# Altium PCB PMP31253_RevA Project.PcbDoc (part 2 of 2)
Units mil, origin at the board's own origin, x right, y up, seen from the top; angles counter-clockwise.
Board outline 7112.5 x 1987.5 mil, 2 copper layers (Top Layer, Bottom Layer), stack 62 mil thick; 96 components, 51 nets, 198 pads, 16 vias.
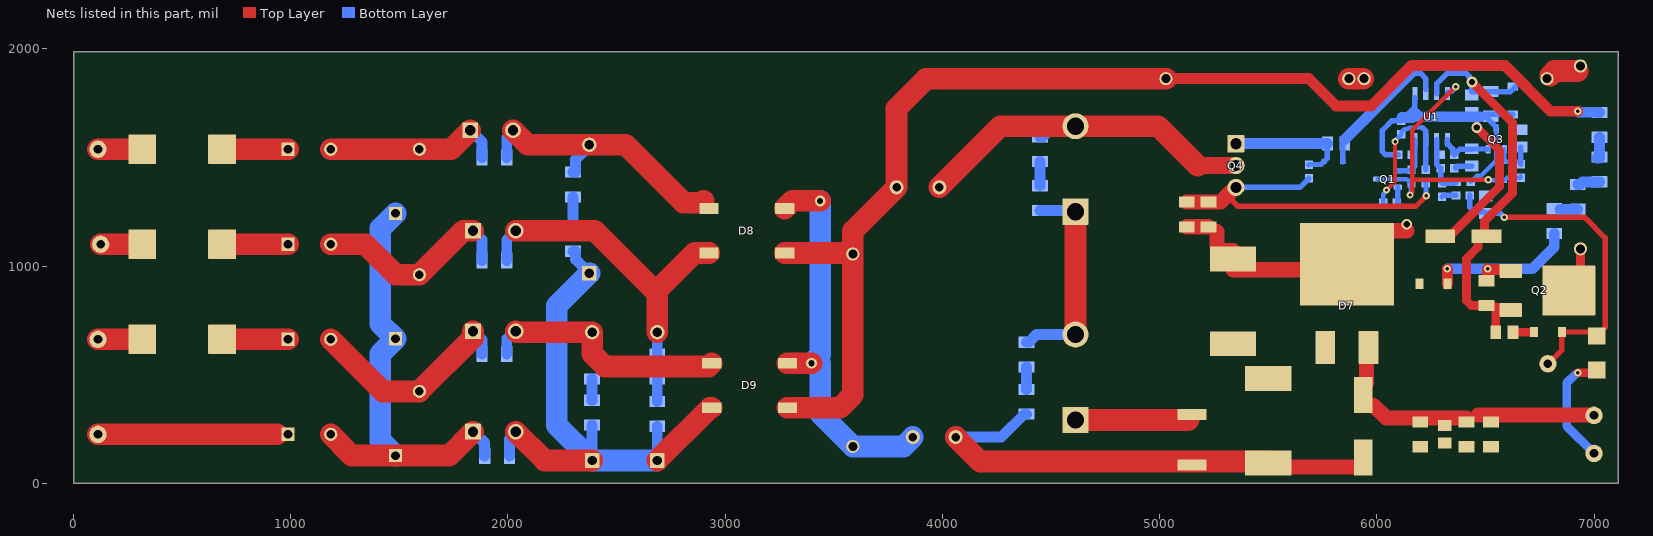
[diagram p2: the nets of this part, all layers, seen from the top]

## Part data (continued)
R20 R31 R39 R44: library part CMP-0087547-1, "RESISTOR, 5W 5% 22R", Manufacturer="TE Connectivity", Power_W=5W, TempCo=300ppm/°C, Tolerance_%=5%
R21 R32 R40 R45: library part CMP-0016578-3, "RES, 10.0 k, 1%, 0.5 W, AEC-Q200 Grade 0, 1206", Manufacturer=Vishay-Dale, Power_W=500mW, Supplier Part Number 1=541-10.0KUCT-ND, TempCo="100 ppm/C", Tolerance_%=1%, Value2=0.5W, Value_Code=10k0, ValueDisplayed=10.0k
R22 R25 R33 R36 R41 R43: library part CMP-0018574-3, "RES, 5%, 1206", Manufacturer=Vishay-Dale, PartNumber=TBD, Power_W=250mW, TempCo="200 ppm/C", Tolerance_%=5%, Value2=0.25W, Value_Code=100k, ValueDisplayed=DNP
R23 R35 R42: library part CMP-0001478-1, "750 V 2.5 kA Varistor 1 Circuit Through Hole Disc 10mm", Clamping Voltage=1240V, Digikey Part Number=495-4644-ND, Manufacturer=TDK, Mouser Part Number=871-B72210S461K101, Operating Temperature Range="-40°C to +105°C", Part Number=B72210S0461K101, ValueDisplayed=150pF, Varistor Voltage=750V, Voltage Tolerance=10%
R24: library part CMP-0017792-3, "RES, 0.56, 1%, 0.25 W, AEC-Q200 Grade 0, 1206", Manufacturer=Panasonic, Power_W=250mW, Supplier Part Number 1=P.56RCT-ND, TempCo="250 ppm/C", Tolerance_%=1%, Value2=0.25W, Value_Code=R560, ValueDisplayed=0.56
R26: library part CMP-0017774-1, Manufacturer=Panasonic, PartNumber=ERJ-8RQF1R2V, Power_W=250mW, Supplier Part Number 1=P1.2RCT-ND, TempCo="200 ppm/C", Tolerance_%=1%, Value2=0.25W, Value_Code=1R20
R27 R30 R34 R38: library part CMP-0018574-3, "RES, 5%, 1206", Manufacturer=Vishay-Dale, PartNumber=750k, Power_W=250mW, TempCo="200 ppm/C", Tolerance_%=5%, Value2=0.25W, Value_Code=100k
R28 R29: library part CMP-0018703-3, "RES, 5.1 k, 5%, 0.25 W, AEC-Q200 Grade 0, 1206", Manufacturer=Vishay-Dale, Power_W=250mW, Supplier Part Number 1=541-5.1KECT-ND, TempCo="200 ppm/C", Tolerance_%=5%, Value2=0.25W, Value_Code=5k10, ValueDisplayed=5.1k
R37: library part CMP-0078952-1, "RES, 15, 1%, 2 W, 2512", Manufacturer=Bourns, Power_W=2W, Supplier Part Number 1=CRM2512-FX-2000ELF-ND, TempCo="100 ppm/C", Tolerance_%=1%, Value_Code=200R, ValueDisplayed=SHORT
TP1 TP2 TP4 TP5 TP6 TP7: library part CMP-0055137-2, "Test Point, Miniature, Red, TH", Color=Red, Manufacturer="Keystone Electronics", Supplier Part Number 1=36-5000-ND
TP3: library part CMP-0055138-2, "Test Point, Miniature, Black, TH", Color=Black, Manufacturer="Keystone Electronics", Supplier Part Number 1=36-5001-ND
U1: library part CMP-0001407-1, "Low-Power Current-Mode High-Performance PWM Controller for Si and SiC MOSFETs", Digikey Part Number=296-UCC28C55DRCT-ND, Manufacturer="Texas Instruments", Max Supply Voltage=28V, Mouser Part Number=595-UCC28C55DR, Nominal Supply Current=1.3mA, Operating Temperature Range="-40°C to +125°C", Switching Frequency=1MHz

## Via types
v1: diameter 34, hole 16, Top Layer to Bottom Layer, 11 vias
v2: diameter 50, hole 28, Top Layer to Bottom Layer, 5 vias

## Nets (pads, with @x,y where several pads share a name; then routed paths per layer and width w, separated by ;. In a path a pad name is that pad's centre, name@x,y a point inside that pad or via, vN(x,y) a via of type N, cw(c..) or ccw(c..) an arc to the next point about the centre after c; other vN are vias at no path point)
12Vout: C12.2 C13.2 C14.2 D1.2 L4.1 L6.2 R28.1 R29.1 R37.1 R38.1 TP5.1 | length 2809.6
  Top Layer w40: v1(6925,508.07) 6999.31,508.07 D1.2@7012.5,521.26
  Top Layer w70: 5612.5,75 5929.19,75 5937.5,83.31 C14.2@5937.5,118.8
  Top Layer w100: L6.2@4062.5,212.5 4175,100 R37.1@5150,100 ; 5218.41,100 R37.1@5150,100 ; L4.1@5500,99.7 5243.7,99.7 5243.41,100 R37.1@5150,100
  Bottom Layer w40: v1@6912.5,500 6875,462.5 6875,262.5 TP5.1@7000,137.5
  Bottom Layer w50: L6.2@4060.93,212.5 4271.26,212.5 4376.67,317.91 R38.1@4387.5,317.91
COMP: C5.2 C7.2 Q3.2 U1.1 | length 234.6
  Bottom Layer w25: U1.1@6325,1581.2 6325,1563.88 6349.31,1539.57 6349.31,1518.7 6355.51,1512.5 C5.2@6356.5,1512.5 6357.48,1512.5 6367.41,1522.43 6367.41,1523.42 6382.06,1538.06 C7.2@6435.56,1538.06 ; C7.2@6451.25,1538.75 6511.81,1538.75 6512.5,1538.06 Q3.2@6512.5,1537.5
CS: Q4.3 R17.1 R19.2 R24.2 R26.1 | length 1626.1
  Top Layer w25: 5315.06,1328.35 5315.06,1321.26 5361.32,1275 6179.17,1275 v1(6227.7,1323.52)
  Top Layer w70: R26.1@5125,1294.59 R24.2@5225,1294.59 5281.3,1294.59 5315.06,1328.35 5348.82,1362.11 Q4.3@5351.18,1362.11
  Bottom Layer w25: Q4.3@5351.18,1362.11 5646.4,1362.11 5687.5,1403.21 R19.2@5687.5,1404.19 ; R17.1@6225,1381 6226.35,1379.66 6226.35,1324.87 v1(6227.7,1323.52)
FB: C1.1 D1.1 D2.2 R16.1 TP1.1 | length 1547.1
  Top Layer w25: v1(6587.5,1223.56) 6957.94,1223.56 7051.4,1130.1 7051.4,717.64 D1.1@7012.5,678.74 6995.01,696.23 D2.2@6851.97,696.23 6851.97,614.47 TP1.1@6787.5,550
  Bottom Layer w25: R16.1@6428.47,1323.89 R16.1@6427.5,1324.87 6427.5,1272.46 6450,1249.96 6493.04,1249.96 C1.1@6500.89,1242.12 6568.7,1242.12 6587.26,1223.56 v1(6587.5,1223.56) v1@6585.9,1225.16
HV_IN: C15.1 D8.1 D9.1 L2.1 R6.2 R11.2 | length 5553.4
  Top Layer w50: R6.2@5029.13,1862.5 5687.5,1862.5 5812.5,1737.5 5975,1737.5 6160,1922.5 6590,1922.5 6800,1712.5 v1(6925,1712.5)
  Top Layer w100: D8.1@3274.5,1060.14 3582.78,1060.14 C15.1@3587.5,1055.41 ; D9.1@3287,347.64 3528.92,347.64 3587.5,406.22 C15.1@3587.5,1055.41 ; R6.2@5029.13,1862.5 3925,1862.5 3789.07,1726.57 L2.1@3789.07,1362.5 3587.5,1160.93 C15.1@3587.5,1055.41
  Bottom Layer w50: v1(6925,1712.5) 6929.82,1707.68 7024.41,1707.68 R11.2@7025,1707.09
NetC2_1: C2.1 C3.1 C6.1 D4.1 Q2.3 R2.1 R7.1 U1.7 | length 2025.7
  Top Layer w40: v2(6437.5,1846.9) 6625,1659.4 6625,1335 6495.56,1205.56 6495.56,1149 6489.02,1149 6466.02,1126 6466.02,1087.5 6412.5,1033.98 6412.5,841.34 6435.93,817.91 R7.1@6504.59,817.91 6510.18,812.32 6546.03,812.32 6547.5,810.85 ; C6.1@6504.59,1144 C6.1@6512.5,1144 ; R2.1@6547.5,695.24 6547.5,810.85 ; Q2.3@6616.14,797.74 6604.65,809.23 6549.12,809.23 6547.5,810.85
  Bottom Layer w25: U1.7@6275,1793.8 6275.69,1794.49 6275.69,1838.19 6325,1887.5 6410.42,1887.5 6425.07,1872.86 6425.07,1866.1 6437.5,1853.66 v2(6437.5,1846.9) 6437.5,1802.5 6615,1802.5 D4.1@6637.5,1825
NetC4_1: C4.1 Q1.1 R1.1 U1.4 | length 209.1
  Bottom Layer w25: Q1.1@6097.24,1437.4 6097.93,1438.09 6161.91,1438.09 R1.1@6162.5,1437.5 ; R1.1@6160.36,1444 6160.36,1444.98 6175,1459.63 U1.4@6175,1581.2
NetC5_1: C5.1 R12.2 R13.2 R14.2 U1.2 | length 260.2
  Bottom Layer w25: U1.2@6275,1581.2 6275,1467.52 R14.2@6287.5,1455.02 ; R12.2@6293.5,1388.98 R14.2@6293.5,1450 ; R12.2@6300,1381.5 6361.32,1381.5 6362.5,1382.68 R13.2@6362.5,1387.5
NetC7_1: C7.1 R14.1 | length 82.1
  Bottom Layer w25: R14.1@6362.5,1450 6362.5,1455.02 6367.48,1460 C7.1@6437.5,1460
NetC8_1: C8.1 D3.2 Q3.1 R3.1 | length 204.7
  Bottom Layer w20: Q3.1@6587.3,1537.5 6587.3,1481 R3.1@6657.03,1481
  Bottom Layer w25: R3.1@6662.5,1469 6662.5,1481 C8.1@6662.5,1547.5
NetC9_1: C9.1 R15.1 R17.2 U1.3 | length 650.9
  Top Layer w20: v1(6044.51,1350) 6083.8,1389.29 v1(6083.8,1573.03)
  Bottom Layer w20: R15.1@6029.19,1291.88 6029.19,1330.89 6044.51,1346.21 v1(6044.51,1350) ; v1(6083.8,1573.03) 6083.8,1576.32 6112.5,1605.02 C9.1@6112.5,1606 ; C9.1@6114.57,1616.43 cw(c6133.28,1609.37) 6132.2,1629.34 ccw(c6131.2,1649.31) 6143.37,1633.44 cw(c6155.45,1617.5) 6155.39,1637.5 6209.67,1637.5
  Bottom Layer w25: 6209.67,1637.5 6224.31,1622.86 6224.31,1581.89 U1.3@6225,1581.2 R17.2@6225,1444
NetC10_1: C10.1 C17.1 C18.1 D9.4 L8.2 R25.1 R36.1 R43.1 R45.2 | length 2633.1
  Top Layer w100: L8.2@2035.93,237.5 2168.7,104.72 C18.1@2387.5,104.72 ; C17.1@2687.5,104.72 2930.41,347.64 D9.4@2938,347.64
  Bottom Layer w50: R45.2@2007.09,125 2007.68,125.59 2007.68,203.07 2035.93,231.32 L8.2@2035.93,237.5 ; R25.1@2300,1067.91 2310.83,1067.91 2311.42,1067.32 2311.42,1030.81 C10.1@2375,967.22 ; C18.1@2387.5,104.72 R43.1@2387.5,267.91 ; C17.1@2687.5,104.72 R36.1@2687.5,262.5
  Bottom Layer w100: C10.1@2375,967.22 2225,817.22 2225,267.22 C18.1@2387.5,104.72 C17.1@2687.5,104.72
NetC10_2: C10.2 D8.3 L1.2 R21.2 R22.2 | length 1324.5
  Top Layer w100: L1.2@2023.43,1625 2090.65,1557.78 C10.2@2375,1557.78 2542.22,1557.78 2808.58,1291.42 2891.42,1291.42 2900,1300
  Bottom Layer w50: R21.2@1994.59,1500 1994.59,1589.98 2023.43,1618.82 L1.2@2023.43,1625 L1.2@2019.06,1620.63 ; R22.2@2300,1432.09 2310.83,1432.09 2311.42,1432.68 2311.42,1489.61 2375,1553.19 C10.2@2375,1557.78
NetC11_1: C11.1 C16.2 R30.1 R34.2 | length 969.9
  Top Layer w100: C16.2@4612.5,684.35 C11.1@4612.5,1250
  Bottom Layer w50: R34.2@4387.5,649.31 4398.33,649.31 4433.37,684.35 C16.2@4612.5,684.35 ; R30.1@4450,1255.41 4450.59,1254.82 4607.68,1254.82 C11.1@4612.5,1250
NetC11_2: C11.2 L2.2 Q4.2 R27.2 | length 1739.6
  Top Layer w80: 5175,1462.5 Q4.2@5351.18,1462.5
  Top Layer w100: L2.2@3985.93,1362.5 4267.13,1643.7 C11.2@4612.5,1643.7 4993.8,1643.7 5175,1462.5
  Bottom Layer w50: R27.2@4450,1594.59 4460.83,1594.59 4496.53,1630.29 4599.09,1630.29 C11.2@4612.5,1643.7
NetC15_2: C15.2 D8.2 D9.2 L6.1 | length 1791.6
  Top Layer w100: D8.2@3274.5,1264.86 3309.64,1300 v2(3437.5,1300) ; D9.2@3287,552.36 v2(3397.64,552.36)
  Bottom Layer w100: v2(3397.64,552.36) 3437.5,592.22 v2(3437.5,1300) ; 3437.5,552.36 3437.5,319.59 C15.2@3587.5,169.59 3821.16,169.59 L6.1@3864.07,212.5
NetC16_1: C16.1 R37.2 | length 521
  Top Layer w100: C16.1@4612.5,290.65 5131.99,290.65 R37.2@5133.07,291.73
NetC17_2: C17.2 D8.4 L5.2 R32.2 R33.2 | length 1527.7
  Top Layer w100: L5.2@2035.93,1162.5 2400,1162.5 2687.5,875 ; C17.2@2687.5,695.28 2687.5,875 ; D8.4@2925.5,1060.14 2860.14,1060.14 2687.5,887.5 2687.5,875
  Bottom Layer w50: R32.2@1994.59,1025 1994.59,1121.16 L5.2@2035.93,1162.5 ; R33.2@2687.5,594.59 C17.2@2687.5,695.28
NetC18_2: C18.2 D9.3 L7.2 R40.2 R41.2 | length 1260.5
  Top Layer w100: L7.2@2035.93,700 2040.65,695.28 C18.2@2387.5,695.28 2387.5,596.08 2446.08,537.5 2923.14,537.5 D9.3@2938,552.36
  Bottom Layer w50: R40.2@1994.59,594.59 1994.59,664.86 2029.75,700 L7.2@2035.93,700 ; R41.2@2387.5,594.59 C18.2@2387.5,695.28
NetD2_1: D2.1 R2.2 | length 95.9
  Top Layer w40: R2.2@6627.5,695.24 6628,695.73 6722.53,695.73 D2.1@6723.03,696.23
NetD3_1: D3.1 Q1.3 R1.2 R3.2 U1.8 | length 1370
  Top Layer w20: v1(6152.95,1327) 6152.95,1330.79 6162.5,1340.33 6162.5,1396.45 ; v1(6362.5,1825) 6162.5,1625 6162.5,1396.45 ; v1(6512.5,1396.45) 6162.5,1396.45
  Bottom Layer w20: Q1.3@6002.76,1400 6137.5,1400 R1.2@6156.25,1381.25 ; v1(6152.95,1327) 6155.63,1329.68 6155.63,1376.28 R1.2@6160.36,1381 ; U1.8@6325,1793.8 6325,1800.69 6326.81,1802.5 6344.78,1802.5 6356.5,1814.22 6356.5,1815.21 6362.5,1821.21 v1(6362.5,1825) ; v1(6512.5,1396.45) 6513.63,1395.32 6586.37,1395.32 D3.1@6587.5,1394.19 6599.31,1406 R3.2@6662.5,1406 ; R3.2@6659.82,1409.82 R3.2@6662.5,1412.5
NetD5_1: D5.1 Q2.1 R7.2 R8.1 | length 835.7
  Top Layer w50: D5.1@6325,917.68 v1(6325,987.5) ; R7.2@6504.59,932.09 6509.59,932.09 6510.18,932.68 v1(6510.18,987.5) 6513.92,983.76 6609.65,983.76 Q2.1@6616.14,977.26
  Bottom Layer w50: v1(6325,987.5) v1(6510.18,987.5) 6716.73,987.5 6816.73,1087.5 R8.1@6816.73,1149.4
NetD6_2: D6.2 Q4.1 R18.1 R19.1 | length 585.5
  Bottom Layer w25: R19.1@5687.5,1467.19 5687.83,1467.52 5743.41,1467.52 D6.2@5756.69,1480.81 5772.5,1496.61 R18.1@5772.5,1563.39
  Bottom Layer w50: Q4.1@5351.18,1562.89 5351.67,1563.39 R18.1@5772.5,1563.39
NetF1_1: F1.1 TP2.1 | length 203.4
  Top Layer w100: TP2.1@112.5,1537.5 F1.1@315.94,1537.5
NetF1_2: F1.2 R20.1 | length 303.4
  Top Layer w100: F1.2@684.06,1537.5 R20.1@987.5,1537.5
NetF2_1: F2.1 TP4.1 | length 190.9
  Top Layer w100: TP4.1@125,1100 F2.1@315.94,1100
NetF2_2: F2.2 R31.1 | length 303.4
  Top Layer w100: F2.2@684.06,1100 R31.1@987.5,1100
NetF3_1: F3.1 TP6.1 | length 203.4
  Top Layer w100: TP6.1@112.5,662.5 F3.1@315.94,662.5
NetF3_2: F3.2 R39.1 | length 303.4
  Top Layer w100: F3.2@684.06,662.5 R39.1@987.5,662.5
NetL1_1: L1.1 R20.2 R21.1 R23.2 | length 836.6
  Top Layer w100: R20.2@1184.35,1537.5 R23.2@1592.62,1537.5 1739.07,1537.5 L1.1@1826.57,1625
  Bottom Layer w50: L1.1@1826.57,1625 1879.82,1571.75 1879.82,1500.59 R21.1@1880.41,1500 R21.1@1880.41,1510.83
NetL3_1: L3.1 L4.2
NetL5_1: L5.1 R31.2 R32.1 R35.2 | length 951.1
  Top Layer w100: R31.2@1184.35,1100 1342.52,1100 1482.38,960.14 R35.2@1592.62,960.14 1794.98,1162.5 L5.1@1839.07,1162.5
  Bottom Layer w50: L5.1@1839.07,1162.5 1880.41,1121.16 R32.1@1880.41,1025
NetL7_1: L7.1 R39.2 R40.1 R42.2 | length 1009.6
  Top Layer w100: R39.2@1184.35,662.5 1424.21,422.64 R42.2@1592.62,422.64 1839.07,669.09 L7.1@1839.07,700
  Bottom Layer w50: L7.1@1839.07,700 1879.82,659.25 1879.82,595.18 R40.1@1880.41,594.59
NetL8_1: L8.1 R23.1 R35.1 R42.1 R44.2 R45.1 | length 2108.1
  Top Layer w100: R44.2@1184.35,225 1281.99,127.36 R42.1@1482.38,127.36 1728.94,127.36 L8.1@1839.07,237.5
  Bottom Layer w50: L8.1@1839.07,237.5 1876.57,200 1879.82,200 1892.32,187.5 1892.32,125.59 R45.1@1892.91,125
  Bottom Layer w100: R42.1@1482.38,127.36 1412.5,197.24 1412.5,594.98 R35.1@1482.38,664.86 1412.5,734.74 1412.5,1172.34 R23.1@1482.38,1242.22
NetQ1_2: Q1.2 R15.2 | length 78.1
  Bottom Layer w25: Q1.2@6097.24,1362.6 6096.31,1362.6 6095.62,1361.91 6095.62,1291.88 R15.2@6100,1287.5
NetQ2_4: Q2.4 R4.1 | length 213.9
  Top Layer w40: Q2.4@6883.86,887.5 6937.5,941.14 R4.1@6937.5,1079.13
NetR4_2: R4.2 R5.1 | length 135.5
  Top Layer w100: R5.1@6797.93,1877.07 6818.37,1897.5 R4.2@6925,1897.5
NetR5_2: R5.2 R6.1 | length 66.6
  Top Layer w100: R6.1@5870.87,1862.5 R5.2@5937.5,1862.5
NetR8_2: R8.2 R9.1 | length 81.4
  Bottom Layer w50: R8.2@6843.8,1260.83 6924.41,1260.83 R9.1@6925,1261.42
NetR9_2: R9.2 R10.1 | length 105.1
  Bottom Layer w50: R9.2@6925,1375.59 6935.83,1375.59 6947.54,1387.3 7024.41,1387.3 R10.1@7025,1387.89
NetR10_2: R10.2 R11.1 | length 111.6
  Bottom Layer w50: R10.2@7025,1496.65 7014.17,1496.65 7025,1507.48 R11.1@7025,1592.91
NetR12_1: R12.1 R16.2 | length 67.2
  Bottom Layer w25: R12.1@6300,1318.5 6300,1318.67 6306.2,1324.87 R16.2@6364.5,1324.87
NetR22_1: R22.1 R25.2 | length 135.8
  Bottom Layer w50: R25.2@2300,1182.09 R22.1@2300,1317.91
NetR27_1: R27.1 R30.2 | length 110.8
  Bottom Layer w50: R30.2@4450,1369.59 R27.1@4450,1480.41
NetR33_1: R33.1 R36.2 | length 103.7
  Bottom Layer w50: R36.2@2687.5,376.67 R33.1@2687.5,480.41
NetR34_1: R34.1 R38.2 | length 103.1
  Bottom Layer w50: R38.2@4387.5,432.09 R34.1@4387.5,535.14
NetR41_1: R41.1 R43.2 | length 98.3
  Bottom Layer w50: R43.2@2387.5,382.09 R41.1@2387.5,480.41
NetR44_1: R44.1 TP7.1 | length 825
  Top Layer w100: TP7.1@112.5,225 937.5,225
OUT: D6.1 R18.2 U1.6 | length 664.5
  Bottom Layer w25: D6.1@5843.31,1480.81 5843.31,1573.03 R18.2@5852.5,1582.22 ; 6157.78,1887.5 6200,1887.5 6225,1862.5 U1.6@6225,1812.5
  Bottom Layer w50: R18.2@5852.5,1582.22 5940.14,1669.86 6157.78,1887.5
PGND: C12.1 C13.1 C14.1 D7.1 D7.3 R28.2 R29.2 TP3.1 | length 1268.2
  Top Layer w70: D7.3@5962.5,592.62 5951.83,581.95 5951.83,459.9 5937.5,445.57 C14.1@5937.5,406.2 5937.5,366.83 5945.81,358.52 5985.18,358.52 6043.7,300 R28.2@6412.5,300 ; 6466.02,314.41 TP3.1@6995.38,314.41
SN: C1.2 C2.2 C3.2 C4.2 C6.2 C8.2 C9.2 D4.2 D5.2 D7.4 L3.2 Q3.3 R13.1 R24.1 R26.2 U1.5 | length 3099.2
  Top Layer w40: C6.2@6291.99,1137.5 6303.49,1149 6347.48,1149 6565,1366.51 6565,1532.5 v2(6460,1637.5)
  Top Layer w50: C6.2@6325,1137.5 C6.2@6331.5,1144
  Top Layer w70: R26.2@5125,1180.41 R24.1@5225,1180.41 ; 5263.92,1157.48 5263.92,1094.25 5288.29,1069.88 L3.2@5337.5,1069.88 ; L3.2@5337.5,982.38 D7.4@5856,982.38 ; D7.4@5861.91,1007.68 6016.87,1162.64 6137.64,1162.64
  Bottom Layer w20: R13.1@6431.5,1387.5 6432.48,1387.5 6459.98,1415 6478.73,1415 6549.9,1486.17 Q3.3@6549.9,1631.99
  Bottom Layer w25: C4.2@6098.52,1512.5 6039.64,1512.5 6025,1527.14 6025,1625 6069,1669 C9.2@6112.5,1669 6112.5,1669.98 6118.7,1676.18 6119.69,1676.18 6174.98,1731.47 U1.5@6174.98,1775.79 ; 6487.5,1687.5 6498.03,1698.03 D4.2@6625,1698.03 ; C3.2@6500.89,1687.5 Q3.3@6549.21,1639.17
  Bottom Layer w50: C9.2@6116.24,1683.76 6164.96,1683.76 6181.2,1700 6193.7,1687.5 6475,1687.5
  other v2: 6137.64,1192.12

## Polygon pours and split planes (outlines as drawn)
PGND on Top Layer "TOP_LAYER_PGND_P014" (solid, pour order 14): 5712.5,690.5 cw(c5739.92,690.5) 5739.92,717.91 6347.58,717.91 cw(c6347.58,690.5) 6375,690.5 6375,497.39 ccw(c6426.82,497.39) 6426.82,445.57 7036.51,445.57 cw(c7036.51,412.5) 7069.58,412.5 7069.58,297.08 cw(c7037.5,297.08) 7037.5,265 5747.5,265 cw(c5747.5,300) 5712.5,300
NetL3_1 on Top Layer "TOP_LAYER_NETL3_1_P005" (solid, pour order 5): 5225,437.5 ccw(c5250,437.5) 5250,412.5 5599.82,412.5 ccw(c5599.82,425) 5612.32,425 5612.32,676.55 ccw(c5585.89,676.55) 5585.89,702.98 5240.48,702.98 ccw(c5240.48,687.5) 5225,687.5
12Vout on Top Layer "TOP_LAYER_12VOUT_P003" (solid, pour order 3): 4022.05,25 4037.5,25 cw(c4037.5,50) 4012.5,50 4012.5,250 cw(c4037.5,250) 4037.5,275 4162.5,275 cw(c4162.5,262.5) 4175,262.5 4175,225 ccw(c4237.5,225) 4237.5,162.5 5752.5,162.5 ccw(c5752.5,185) 5775,185 5775,187.5 cw(c5812.5,187.5) 5812.5,225 7050,225 cw(c7050,200) 7075,200 7075,37.5 cw(c7062.5,37.5) 7062.5,25 4037.5,25 cw(c4037.5,50) 4015.14,38.82
PGND on Top Layer "TOP_LAYER_PGND_P001" (solid, pour order 1): 5712.5,362.5 ccw(c5750,362.5) 5750,325 6028.69,325 ccw(c6028.69,362.5) 6066.19,362.5 6066.19,676.72 ccw(c6025,676.72) 6025,717.91 5742.91,717.91 ccw(c5742.91,687.5) 5712.5,687.5
SN on Top Layer "TOP_LAYER_SN_P000" (solid, pour order 0): 5087.5,1212.5 cw(c5100,1212.5) 5100,1225 6212.5,1225 cw(c6212.5,1187.5) 6250,1187.5 6250,832.09 cw(c6221.46,841.04) 6212.5,812.5 5650,812.5 cw(c5650,850) 5612.5,850 5612.5,900 ccw(c5575,900) 5575,937.5 5112.5,937.5 cw(c5112.5,962.5) 5087.5,962.5
SN on Bottom Layer "BOTTOM_LAYER_SN_P012" (solid, pour order 12): 6152.34,1737.5 ccw(c6152.34,1637.51) 6081.63,1708.21 5962.5,1605.02 ccw(c5996.49,1561.43) 5941.63,1568.21 5941.63,1187.5 ccw(c5971.68,1192.54) 5976.72,1162.5 6725,1162.5 ccw(c6725,1187.5) 6750,1187.5 6750,1687.5 ccw(c6700,1687.5) 6700,1737.5
NetC2_1 on Bottom Layer "BOTTOM_LAYER_NETC2_1_P011" (solid, pour order 11): 6400.3,1784.45 ccw(c6408.96,1784.45) 6408.96,1775.79 6656.99,1775.79 ccw(c6656.99,1793.8) 6675,1793.8 6675,1900 ccw(c6662.5,1900) 6662.5,1912.5 6425.3,1912.5 ccw(c6425.3,1887.5) 6400.3,1887.5

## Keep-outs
Keep-Out Layer:
  text ".Layer_Name" at 577,-858.49 h60

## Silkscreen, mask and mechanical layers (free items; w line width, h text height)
Top Overlay:
  text "PMP31253_RevA" at 197.5,1845 h60
  text ".Layer_Name" at 577,-858.49 h50
Bottom Overlay:
  text ".Layer_Name" at 577,-858.49 h40
Top Paste:
  text ".Layer_Name" at 577,-858.49 h60
Bottom Paste:
  text ".Layer_Name" at 577,-858.49 h60
Top Solder:
  text ".Layer_Name" at 577,-858.49 h60
  text ".Layer_Name" at 577,-858.49 h60
Bottom Solder:
  text ".Layer_Name" at 577,-858.49 h60
Drill Guide:
  text ".Layer_Name" at 577,-858.49 h60
M1 Board Outline:
  the board outline again, w10
  text ".Layer_Name" at 577,-858.49 h60
M2 Board Dimensions:
  rectangle: 125,-400 500,-275
  rectangle: 0,-275 125,-150
  lines w7: 0,-275 1000,-275 ; 125,-400 125,-150 ; 250,-400 250,-150 ; 500,-400 500,-150 ; 750,-400 750,-150 ; 0,-400 0,-150 1000,-150 1000,-400 0,-400
  text ".Layer_Name" at 577,-858.49 h60
M3 3D STEP Top:
  text ".Layer_Name" at 577,-858.49 h60
M4 3D STEP Bottom:
  text ".Layer_Name" at 577,-858.49 h60
Top M5 Assembly Top/M6 Assembly Bottom:
  lines w10: -292,-930.17 6308,-930.17 ; -292,-726.83 6310,-726.83 ; -292,-523.5 -292,-1133.5 3713,-1133.5 6310,-1133.5 6310,-523.5 -291.5,-523.5 -291.5,-1133.5 1284,-1133.5 ; 2173,-1133.5 2173,-523.5 ; 3440,-726.83 3440,-523.5 ; 4280,-726.83 4280,-523.5 ; 4902,-1140 4902,-937.17
  text "COMPONENTS MARKED 'DNP' SHOULD NOT BE POPULATED." at 1153.5,-318.5 h60
  text "ASSEMBLY VARIANT:" at 1153,-434 h60
  text ".VariantName" at 2189,-434 h60
  text "PCB VIEWED FROM TOP SIDE" at -228.5,-655.67 h60
  text "BOARD #:" at 2248,-655.67 h60
  text ".PRJ_Number" at 2793.5,-655.67 h60
  text "REV:" at 3638,-655.67 h60
  text ".PCB_Rev" at 3929.5,-655.67 h60
  text "SVN REV:" at 4476,-655.67 h60
  text ".VersionControl_RevNumber" at 4982,-655.67 h60
  text "PLOT NAME =" at -228.5,-1064.34 h60
  text ".plot_File_Name" at 577,-1064.34 h60
  text "GENERATED    :" at 2250,-1064.34 h60
  text ".Print_Date" at 3119.5,-1064.34 h60
  text ".Print_Time" at 3848.5,-1064.34 h60
  text "TEXAS INSTRUMENTS" at 5113,-1064.34 h60
Bottom M5 Assembly Top/M6 Assembly Bottom:
  lines w10: -292.5,-727.33 6309.5,-727.33 ; -290.5,-930.67 6309.5,-930.67 ; 1115.5,-1140.5 1115.5,-937.67 ; 1737.5,-727.33 1737.5,-524 ; 2577.5,-727.33 2577.5,-524 ; 3844.5,-1134 3844.5,-524 ; 4733.5,-1134 6309,-1134 6309,-524 -292.5,-524 -292.5,-1134 2304.5,-1134 6309.5,-1134 6309.5,-524
  text "COMPONENTS MARKED 'DNP' SHOULD NOT BE POPULATED." at 6102,-318 h60
  text ".VariantName" at 5058,-434 h60
  text "ASSEMBLY VARIANT:" at 6097,-434 h60
  text ".VersionControl_RevNumber" at 1035.5,-656.17 h60
  text "SVN REV:" at 1541.5,-656.17 h60
  text ".PCB_Rev" at 2088,-656.17 h60
  text "REV:" at 2379.5,-656.17 h60
  text ".PRJ_Number" at 3224,-656.17 h60
  text "BOARD #:" at 3769.5,-656.17 h60
  text "PCB VIEWED FROM BOTTOM SIDE" at 6246,-656.17 h60
  text "TEXAS INSTRUMENTS" at 904.5,-1064.84 h60
  text ".Print_Time" at 2169,-1064.84 h60
  text ".Print_Date" at 2898,-1064.84 h60
  text "GENERATED    :" at 3767.5,-1064.84 h60
  text ".plot_File_Name" at 5440.5,-1064.84 h60
  text "PLOT NAME =" at 6246,-1064.84 h60
M9 Title Sheet:
  drawing of 56 lines, arcs and shapes, not listed
  text "1" at 1058.34,13381.39 h70
  text "2" at 4384,13381.39 h70
  text "3" at 7714,13381.39 h70
  text "4" at 11049,13381.39 h70
  text "5" at 14374,13381.39 h70
  text "6" at 17709,13381.39 h70
  text "A" at -463,11603.39 h70
  text "A" at 19237,11603.39 h70
  text "B" at -463,7853.39 h70
  text "B" at 19237,7853.39 h70
  text "C" at -463,4103.39 h70
  text "C" at 19237,4103.39 h70
  text "D" at -463,353.39 h70
  text "D" at 19237,353.39 h70
  text "PROJECT TITLE:" at 16143,268.39 h45
  text ".PRJ_Title" at 16193,135.06 h70
  text "DESIGNED FOR:" at 16143,-32.61 h45
  text ".PRJ_Customer" at 16193,-172.61 h70
  text "FILE NAME:" at 16143,-332.61 h45
  text ".PCB_File_Name_No_Path" at 16193,-452.61 h70
  text "Texas Instruments (TI) and/or its licensors do not warrant the accuracy or completeness of this specification" at 11173.5,-614.45 h45
  text "ENGINEER:" at 16143,-622.61 h45
  text "LAYOUT BY:" at 17648,-622.61 h45
  text "or any information contained therein. TI and/or its licensors do not warrant that this design will meet" at 11128.51,-727.11 h45
  text ".PRJ_Engineer" at 16193,-777.6 h70
  text ".PCB_Layout" at 17698.5,-777.6 h70
  text "the specifications, will be suitable for your application or fit for any particular purpose, or will operate in" at 11128.51,-839.78 h45
  text ".Layer_Name" at 577,-858.49 h60
  text "ALTIUM DESIGNER VERSION:" at 17648,-932.61 h45
  text "an implementation. TI and/or its licensors do not warrant that the design is production worthy. You should" at 11128.51,-952.44 h45
  text "completely validate and test your design implementation to confirm the system functionality for your application." at 11173.5,-1065.11 h45
  text ".print_Scale" at 16193,-1065.94 h70
  text ".Application_BuildNumber" at 17698.5,-1065.94 h70
  text "1" at 1058.34,-1318.61 h70
  text "2" at 4384,-1318.61 h70
  text "3" at 7714,-1318.61 h70
  text "4" at 11049,-1318.61 h70
  text "5" at 14374,-1318.61 h70
  text "6" at 17709,-1318.61 h70
M10 Fab Notes:
  text ".Layer_Name" at 577,-858.49 h60
M11 Gerber Information:
  lines w10: -292,-930.17 6308,-930.17 ; -292,-726.83 6310,-726.83 ; -292,-523.5 -292,-1133.5 3713,-1133.5 6310,-1133.5 6310,-523.5 -291.5,-523.5 -291.5,-1133.5 1284,-1133.5 ; 2173,-1133.5 2173,-523.5 ; 3440,-726.83 3440,-523.5 ; 4280,-726.83 4280,-523.5 ; 4902,-1140 4902,-937.17
  text "ALL ARTWORK VIEWED FROM TOP SIDE" at -228.5,-655.67 h60
  text "BOARD #:" at 2248,-655.67 h60
  text ".PRJ_Number" at 2793.5,-655.67 h60
  text "REV:" at 3638,-655.67 h60
  text ".PCB_Rev" at 3929.5,-655.67 h60
  text "SVN REV:" at 4476,-655.67 h60
  text ".VersionControl_RevNumber" at 4982,-655.67 h60
  text "LAYER NAME =" at -228.5,-858.49 h60
  text "PLOT NAME =" at -228.5,-1064.34 h60
  text ".plot_File_Name" at 577,-1064.34 h60
  text "GENERATED    :" at 2250,-1064.34 h60
  text ".Print_Date" at 3119.5,-1064.34 h60
  text ".Print_Time" at 3848.5,-1064.34 h60
  text "TEXAS INSTRUMENTS" at 5113,-1064.34 h60
M12 Stackup:
  text ".Layer_Name" at 577,-858.49 h60
M13 Component Bodies Top:
  text ".Layer_Name" at 577,-858.49 h60
M14 Component Bodies Bottom:
  text ".Layer_Name" at 577,-858.49 h60
M15 Courtyards Top:
  text ".Layer_Name" at 577,-858.49 h60
M16 Courtyards Bottom:
  text ".Layer_Name" at 577,-858.49 h60
Drill Drawing:
  text ".Layer_Name" at 577,-858.49 h60
M17 Embedded Cavity:
  text ".Layer_Name" at 577,-858.49 h60
M18 Embedded Assembly:
  text ".Layer_Name" at 577,-858.49 h60
M19 Embedded Keepout:
  text ".Layer_Name" at 567,-858.49 h60

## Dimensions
0,-400 to 1000,-400 on M2 Board Dimensions
0,0 to 7112.5,0 on M2 Board Dimensions
0,0 to 0,1987.5 on M2 Board Dimensions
